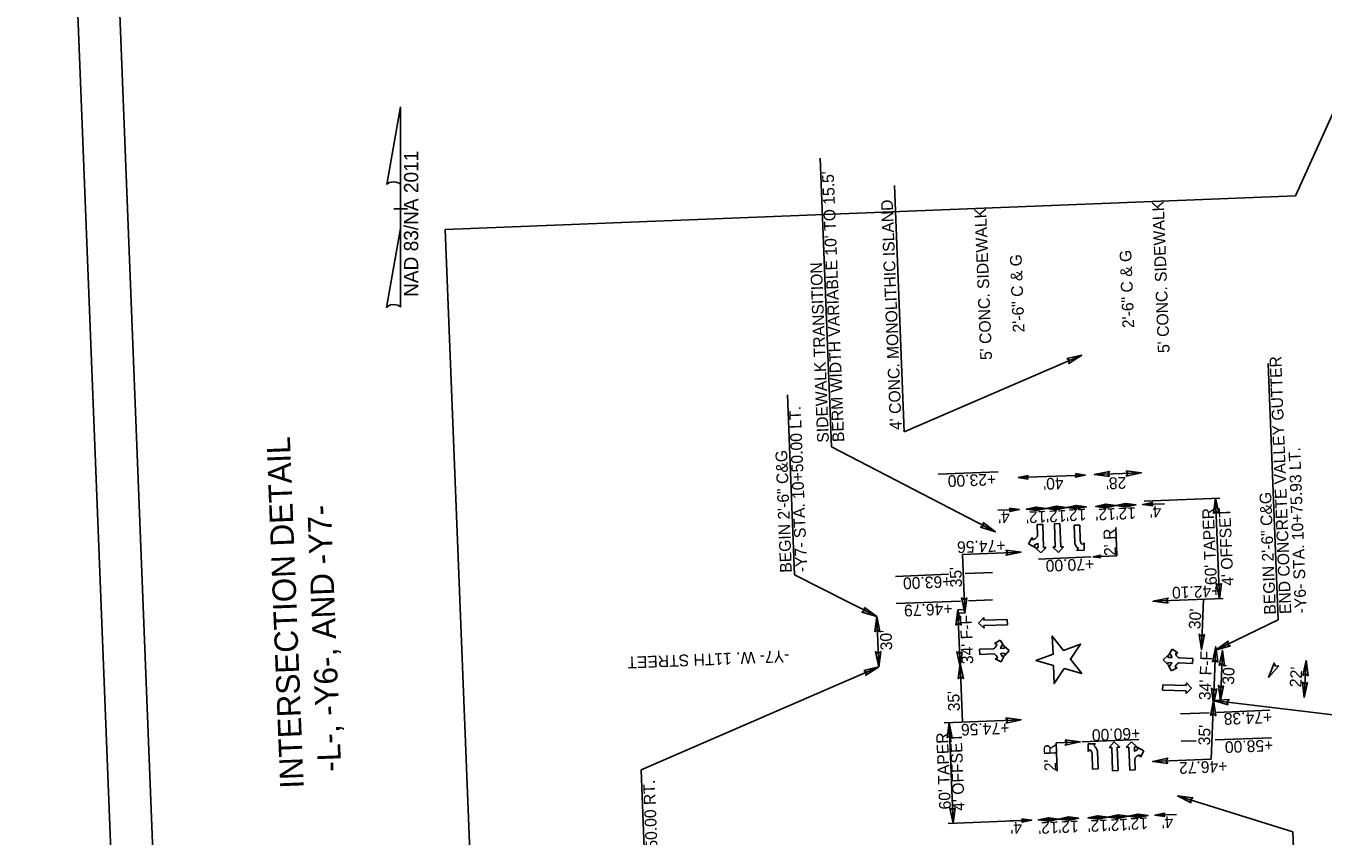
# Model space of a CAD drawing. Extents: x 1627811 to 1628977, y 762656 to 764629.
# Drawn here: x 1627811 to 1628584, y 763078 to 763561 of the extents above; entities that cross this region are included whole.
import ezdxf

# ---------------------------------------------------------------- set-up
doc = ezdxf.new("R2010")
doc.units = 0
for name, color, linetype in [('Prop Conc 2ft 6in Curb and Gutter', 7, 'Continuous'), ('Prop Dimension', 7, 'Continuous'), ('Prop Dimension Text', 7, 'Continuous'), ('Prop DSN Text', 7, 'Continuous'), ('Prop EOT', 7, 'Continuous'), ('Prop Lane Arrow CELL', 7, 'Continuous'), ('Prop North Arrow NAD83 for Plan Sheets CELL', 7, 'Continuous'), ('Prop RDY Traffic Signal CELL', 7, 'Continuous'), ('Prop Terminator CELL', 7, 'Continuous'), ('Sheet Clip Boundary CELL', 7, 'Continuous'), ('Sheet Plan And Profile CELL', 7, 'Continuous'), ('Sheet Plot Border Outside CELL', 7, 'Continuous')]:
    doc.layers.add(name, color=color, linetype=linetype)

msp = doc.modelspace()

# ---------------------------------------------------------------- linework, layer by layer
at = {"layer": 'Prop Conc 2ft 6in Curb and Gutter'}
for p, q in [((1628366.58, 763213.15), (1628370.61, 763213.31)), ((1628369.57, 763213.27), (1628369.61, 763213.27))]:
    msp.add_line(p, q, dxfattribs=at)
at = {"layer": 'Prop Dimension'}
for p, q in [((1628291.09, 763310.38), (1628284.3, 763482.61)), ((1628334.45, 763319.33), (1628328.65, 763466.35)), ((1628334.45, 763319.33), (1628440.42, 763365.19)), ((1628557.67, 763207.22), (1628551.64, 763360.16)), ((1628269.02, 763234.01), (1628264.79, 763341.42)), ((1628388.88, 763259.68), (1628291.09, 763310.38)), ((1628354.82, 763294.19), (1628390.49, 763295.6)), ((1628402.52, 763292.04), (1628442.49, 763293.62)), ((1628447.99, 763293.84), (1628475.96, 763294.94)), ((1628407.27, 763273.24), (1628419.26, 763273.71)), ((1628419.26, 763273.71), (1628431.25, 763274.19)), ((1628431.25, 763274.19), (1628443.24, 763274.66)), ((1628448.73, 763274.88), (1628460.72, 763275.35)), ((1628460.72, 763275.35), (1628472.72, 763275.82)), ((1628476.85, 763275.99), (1628489.72, 763276.49)), ((1628477.58, 763278.11), (1628522.84, 763279.9)), ((1628520.23, 763279.79), (1628522.6, 763219.84)), ((1628390.28, 763272.57), (1628403.27, 763273.08)), ((1628460.75, 763262.23), (1628461.41, 763245.35)), ((1628404.27, 763247.66), (1628369.3, 763246.28)), ((1628370.69, 763211.31), (1628369.3, 763246.28)), ((1628414.62, 763243.51), (1628445.78, 763244.74)), ((1628447.17, 763244.79), (1628461.41, 763245.35)), ((1628387.14, 763235.42), (1628370.91, 763234.78)), ((1628318.07, 763209.21), (1628269.02, 763234.01)), ((1628360.98, 763234.39), (1628329.24, 763233.14)), ((1628482.99, 763218.28), (1628524.77, 763219.93)), ((1628511.78, 763189.48), (1628512.97, 763219.46)), ((1628368.13, 763218.45), (1628329.63, 763216.93)), ((1628366.58, 763213.15), (1628367.93, 763179.17)), ((1628387.22, 763219.2), (1628372.94, 763218.64)), ((1628319.26, 763179.28), (1628318.07, 763209.18)), ((1628520.3, 763189.15), (1628557.67, 763207.22)), ((1628520.3, 763189.15), (1628519.03, 763157.17)), ((1628523.17, 763159.01), (1628524.36, 763188.98)), ((1628367.85, 763181.17), (1628369.24, 763146.2)), ((1628574.33, 763182.88), (1628573.11, 763160.91)), ((1628319.26, 763179.24), (1628177.51, 763117.78)), ((1628519.11, 763159.17), (1628517.72, 763124.2)), ((1628628.35, 763145.87), (1628519.11, 763159.17)), ((1628499.31, 763151.15), (1628516.34, 763151.82)), ((1628520.76, 763152), (1628552.65, 763153.26)), ((1628404.22, 763147.58), (1628358.25, 763145.77)), ((1628363.61, 763085.93), (1628361.25, 763145.88)), ((1628439.51, 763134.4), (1628425.09, 763133.84)), ((1628440.73, 763134.45), (1628474.48, 763135.78)), ((1628508.7, 763135.13), (1628499.76, 763134.78)), ((1628553.72, 763136.91), (1628520.1, 763135.58)), ((1628425.09, 763133.84), (1628425.75, 763116.96)), ((1628482.75, 763122.82), (1628517.72, 763124.2)), ((1628181.73, 763010.81), (1628177.51, 763117.78)), ((1628566.4, 763080.81), (1628497.61, 763102.15)), ((1628414.57, 763087.94), (1628426.56, 763088.41)), ((1628426.56, 763088.41), (1628438.55, 763088.89)), ((1628444.05, 763089.1), (1628456.04, 763089.58)), ((1628456.04, 763089.58), (1628468.03, 763090.05)), ((1628468.03, 763090.05), (1628480.02, 763090.52)), ((1628484.02, 763090.68), (1628496.89, 763091.19)), ((1628409.88, 763087.76), (1628360.62, 763085.81)), ((1628397.59, 763087.27), (1628410.58, 763087.78)), ((1628573.2, 762908.58), (1628566.4, 763080.81))]:
    msp.add_line(p, q, dxfattribs=at)
at = {"layer": 'Prop EOT'}
for p, q in [((1628366.66, 763211.15), (1628370.69, 763211.31)), ((1628369.65, 763211.27), (1628369.69, 763211.27))]:
    msp.add_line(p, q, dxfattribs=at)
at = {"layer": 'Prop Lane Arrow CELL'}
for p, q in [((1628413.83, 763264), (1628417.13, 763264.11)), ((1628414.06, 763257.55), (1628413.83, 763264)), ((1628417.13, 763264.11), (1628417.62, 763250.32)), ((1628424.13, 763264.57), (1628427.43, 763264.69)), ((1628424.63, 763250.58), (1628424.13, 763264.57)), ((1628427.43, 763264.69), (1628427.93, 763250.69)), ((1628439.21, 763263.77), (1628435.91, 763263.65)), ((1628435.91, 763263.65), (1628436.29, 763253.1)), ((1628439.54, 763254.62), (1628439.21, 763263.77)), ((1628408.69, 763252.5), (1628410.75, 763256.43)), ((1628412.62, 763250.44), (1628408.69, 763252.5)), ((1628410.75, 763256.43), (1628411.2, 763255.05)), ((1628412.16, 763251.88), (1628412.62, 763250.44)), ((1628414.32, 763250.2), (1628414.22, 763253.05)), ((1628423.14, 763250.52), (1628424.63, 763250.58)), ((1628426.45, 763247.49), (1628423.14, 763250.52)), ((1628429.43, 763250.75), (1628426.45, 763247.49)), ((1628427.93, 763250.69), (1628429.43, 763250.75)), ((1628441.79, 763253.25), (1628440.78, 763252.16)), ((1628441.9, 763248.75), (1628441.79, 763253.25)), ((1628412.83, 763250.15), (1628414.32, 763250.2)), ((1628416.09, 763247.17), (1628412.83, 763250.15)), ((1628419.12, 763250.38), (1628416.09, 763247.17)), ((1628417.62, 763250.32), (1628419.12, 763250.38)), ((1628438.51, 763249.73), (1628437.5, 763248.64)), ((1628437.5, 763248.64), (1628441.9, 763248.75)), ((1628378.88, 763205.25), (1628381.92, 763208.56)), ((1628382.13, 763202.26), (1628378.88, 763205.25)), ((1628381.92, 763208.56), (1628381.97, 763207.06)), ((1628381.97, 763207.06), (1628395.97, 763207.52)), ((1628396.08, 763204.23), (1628382.08, 763203.76)), ((1628395.97, 763207.52), (1628396.08, 763204.23)), ((1628382.08, 763203.76), (1628382.13, 763202.26)), ((1628379.5, 763189.64), (1628387.78, 763190)), ((1628379.63, 763186.62), (1628379.5, 763189.64)), ((1628388.43, 763193.05), (1628391.75, 763195.15)), ((1628389.71, 763192.72), (1628388.43, 763193.05)), ((1628391.75, 763195.15), (1628393.9, 763191.78)), ((1628391.77, 763190.17), (1628394.26, 763190.28)), ((1628393.9, 763191.78), (1628392.62, 763192.11)), ((1628394.26, 763190.28), (1628394.2, 763191.55)), ((1628394.2, 763191.55), (1628397.19, 763188.94)), ((1628397.19, 763188.94), (1628394.44, 763185.99)), ((1628492.28, 763186.3), (1628494.43, 763189.72)), ((1628494.43, 763189.72), (1628497.75, 763187.58)), ((1628387.86, 763186.98), (1628379.63, 763186.62)), ((1628388.82, 763183.99), (1628390.07, 763184.44)), ((1628392.32, 763182.14), (1628388.82, 763183.99)), ((1628394.39, 763187.26), (1628391.86, 763187.15)), ((1628394.16, 763185.74), (1628392.32, 763182.14)), ((1628392.91, 763185.29), (1628394.16, 763185.74)), ((1628394.44, 763185.99), (1628394.39, 763187.26)), ((1628488.99, 763183.36), (1628491.98, 763186.06)), ((1628491.75, 763180.51), (1628488.99, 763183.36)), ((1628491.8, 763181.78), (1628491.75, 763180.51)), ((1628494.28, 763181.67), (1628491.8, 763181.78)), ((1628491.98, 763186.06), (1628491.93, 763184.8)), ((1628491.93, 763184.8), (1628494.46, 763184.69)), ((1628493.57, 763186.63), (1628492.28, 763186.3)), ((1628497.75, 763187.58), (1628496.47, 763187.24)), ((1628506.56, 763181.15), (1628498.28, 763181.5)), ((1628498.45, 763184.52), (1628506.69, 763184.17)), ((1628506.69, 763184.17), (1628506.56, 763181.15)), ((1628493.88, 763176.71), (1628492.03, 763180.26)), ((1628492.03, 763180.26), (1628493.28, 763179.81)), ((1628497.37, 763178.52), (1628493.88, 763176.71)), ((1628496.12, 763178.96), (1628497.37, 763178.52)), ((1628488.69, 763165.25), (1628488.8, 763168.55)), ((1628488.8, 763168.55), (1628502.79, 763168.1)), ((1628505.88, 763166.4), (1628502.63, 763163.3)), ((1628502.79, 763168.1), (1628502.84, 763169.6)), ((1628502.84, 763169.6), (1628505.88, 763166.4)), ((1628502.68, 763164.8), (1628488.69, 763165.25)), ((1628502.63, 763163.3), (1628502.68, 763164.8)), ((1628456.77, 763131.12), (1628459.75, 763134.38)), ((1628459.75, 763134.38), (1628463.06, 763131.34)), ((1628467.01, 763131.3), (1628470.05, 763134.52)), ((1628470.05, 763134.52), (1628473.31, 763131.53)), ((1628448.57, 763133.31), (1628444.18, 763133.2)), ((1628444.18, 763133.2), (1628444.29, 763128.7)), ((1628444.29, 763128.7), (1628445.3, 763129.79)), ((1628446.54, 763127.33), (1628446.87, 763118.19)), ((1628447.56, 763132.22), (1628448.57, 763133.31)), ((1628450.16, 763118.3), (1628449.79, 763128.85)), ((1628458.27, 763131.17), (1628456.77, 763131.12)), ((1628458.77, 763117.18), (1628458.27, 763131.17)), ((1628463.06, 763131.34), (1628461.56, 763131.29)), ((1628461.56, 763131.29), (1628462.07, 763117.3)), ((1628468.51, 763131.36), (1628467.01, 763131.3)), ((1628469.01, 763117.57), (1628468.51, 763131.36)), ((1628473.31, 763131.53), (1628471.81, 763131.48)), ((1628471.81, 763131.48), (1628471.91, 763128.63)), ((1628473.97, 763129.8), (1628473.52, 763131.24)), ((1628473.52, 763131.24), (1628477.45, 763129.18)), ((1628475.38, 763125.25), (1628474.93, 763126.64)), ((1628477.45, 763129.18), (1628475.38, 763125.25)), ((1628472.07, 763124.13), (1628472.3, 763117.69)), ((1628446.87, 763118.19), (1628450.16, 763118.3)), ((1628462.07, 763117.3), (1628458.77, 763117.18)), ((1628472.3, 763117.69), (1628469.01, 763117.57))]:
    msp.add_line(p, q, dxfattribs=at)
for centre, radius, start, end in [((1628410.14, 763259.36), 4.43, 283.76826, 314.62182), ((1628411.11, 763256.2), 4.43, 283.64945, 314.52805), ((1628411.6, 763258.1), 2.52, 311.13173, 347.44373), ((1628441.43, 763254.08), 5.25, 190.73466, 236.04636), ((1628442.79, 763254.73), 3.28, 182.05859, 231.71676), ((1628386.99, 763192.13), 2.28, 290.42043, 323.41838), ((1628385.76, 763193.35), 4, 319.92829, 351.14097), ((1628388.67, 763192.7), 4, 320.73475, 351.51122), ((1628387.31, 763184.77), 2.28, 41.56467, 76.33069), ((1628386.19, 763183.45), 4, 14.12461, 45.05475), ((1628389.03, 763184.34), 4, 13.75542, 44.64511), ((1628497.16, 763178.89), 4, 135.81592, 166.59239), ((1628497.52, 763187.25), 4, 188.83659, 219.72628), ((1628500, 763177.99), 4, 135.00946, 166.22214), ((1628500.42, 763187.89), 4, 189.20578, 220.13593), ((1628498.88, 763179.31), 2.28, 105.50161, 138.49955), ((1628499.19, 763186.68), 2.28, 216.64584, 251.41186), ((1628443.28, 763127.22), 3.28, 2.05859, 51.71676), ((1628444.64, 763127.87), 5.25, 10.73466, 56.04636), ((1628475.02, 763125.48), 4.43, 103.64945, 134.52805), ((1628475.99, 763122.33), 4.43, 103.76826, 134.62182), ((1628474.54, 763123.58), 2.52, 131.13173, 167.44373)]:
    msp.add_arc(centre, radius, start, end, dxfattribs=at)
at = {"layer": 'Prop North Arrow NAD83 for Plan Sheets CELL'}
for p, q in [((1628025.77, 763466.96), (1628033.99, 763513.3)), ((1628034.04, 763513.3), (1628033.99, 763513.3)), ((1628034.04, 763513.3), (1628033.99, 763513.3)), ((1628034.04, 763513.3), (1628034.02, 763465.5)), ((1628034.01, 763440.7), (1628034.02, 763466.9)), ((1628034.02, 763465.5), (1628034.02, 763466.85)), ((1628030.02, 763452.3), (1628029.97, 763452.3)), ((1628033.57, 763452.3), (1628030.02, 763452.3)), ((1628030.07, 763452.3), (1628038.07, 763452.3)), ((1628034.01, 763440.7), (1628025.64, 763393.46)), ((1628034.04, 763393.65), (1628034.01, 763440.7))]:
    msp.add_line(p, q, dxfattribs=at)
for centre, start_param, end_param in [((1628029.91, 763466.46), 0.216388, 2.908219), ((1628029.88, 763393.29), 0.201328, 3.141593)]:
    msp.add_ellipse(centre, major_axis=(4.23, -0.03), ratio=0.461098, start_param=start_param, end_param=end_param, dxfattribs=at)
at = {"layer": 'Prop RDY Traffic Signal CELL'}
msp.add_lwpolyline([(1628423.53, 763179.98), (1628423.96, 763169.18), (1628429.96, 763178.17), (1628440.4, 763175.23), (1628433.68, 763183.74), (1628439.69, 763192.75), (1628429.54, 763189), (1628422.84, 763197.49), (1628423.27, 763186.68), (1628413.1, 763182.92), (1628423.53, 763179.98)], dxfattribs=at)
at = {"layer": 'Prop Terminator CELL'}
for points in [[(1628431.54, 763363.04), (1628440.42, 763365.19), (1628432.75, 763360.12), (1628433.17, 763362.05)], [(1628408.4, 763291.21), (1628402.52, 763292.04), (1628408.37, 763293.26), (1628407.65, 763292.2)], [(1628436.61, 763294.45), (1628442.49, 763293.62), (1628436.64, 763292.4), (1628437.36, 763293.47)], [(1628457.04, 763292.64), (1628447.99, 763293.84), (1628456.97, 763295.79), (1628455.88, 763294.15)], [(1628466.91, 763296.14), (1628475.96, 763294.94), (1628466.98, 763292.99), (1628468.07, 763294.63)], [(1628397.38, 763273.86), (1628403.27, 763273.08), (1628397.43, 763271.81), (1628398.14, 763272.88)], [(1628413.15, 763272.47), (1628407.27, 763273.24), (1628413.1, 763274.51), (1628412.4, 763273.44)], [(1628413.37, 763274.49), (1628419.26, 763273.71), (1628413.42, 763272.44), (1628414.13, 763273.51)], [(1628425.14, 763272.94), (1628419.26, 763273.71), (1628425.09, 763274.99), (1628424.39, 763273.92)], [(1628425.36, 763274.96), (1628431.25, 763274.19), (1628425.41, 763272.92), (1628426.12, 763273.98)], [(1628437.13, 763273.41), (1628431.25, 763274.19), (1628437.08, 763275.46), (1628436.38, 763274.39)], [(1628437.35, 763275.44), (1628443.24, 763274.66), (1628437.4, 763273.39), (1628438.11, 763274.46)], [(1628454.62, 763274.1), (1628448.73, 763274.88), (1628454.57, 763276.15), (1628453.87, 763275.08)], [(1628454.84, 763276.13), (1628460.72, 763275.35), (1628454.89, 763274.08), (1628455.59, 763275.15)], [(1628466.61, 763274.57), (1628460.72, 763275.35), (1628466.56, 763276.62), (1628465.86, 763275.55)], [(1628466.83, 763276.6), (1628472.72, 763275.82), (1628466.88, 763274.55), (1628467.58, 763275.62)], [(1628482.74, 763275.21), (1628476.85, 763275.99), (1628482.69, 763277.26), (1628481.98, 763276.19)], [(1628519.04, 763270.74), (1628520.23, 763279.79), (1628522.19, 763270.81), (1628520.54, 763271.9)], [(1628381.6, 763265.2), (1628388.88, 763259.68), (1628380.1, 763262.42), (1628381.86, 763263.31)], [(1628395.22, 763248.85), (1628404.27, 763247.66), (1628395.29, 763245.71), (1628396.38, 763247.35)], [(1628451.7, 763244.19), (1628447.17, 763244.79), (1628451.66, 763245.77), (1628451.12, 763244.95)], [(1628523.79, 763228.89), (1628522.6, 763219.84), (1628520.64, 763228.82), (1628522.29, 763227.73)], [(1628371.88, 763220.36), (1628370.69, 763211.31), (1628368.73, 763220.29), (1628370.38, 763219.2)], [(1628492.04, 763217.08), (1628482.99, 763218.28), (1628491.97, 763220.23), (1628490.88, 763218.59)], [(1628310.73, 763214.66), (1628318.07, 763209.21), (1628309.27, 763211.87), (1628311.02, 763212.78)], [(1628365.39, 763204.09), (1628366.58, 763213.15), (1628368.54, 763204.17), (1628366.89, 763205.25)], [(1628316.88, 763200.16), (1628318.07, 763209.21), (1628320.03, 763200.23), (1628318.38, 763201.32)], [(1628513.68, 763198.41), (1628511.78, 763189.48), (1628510.54, 763198.59), (1628512.09, 763197.38)], [(1628518.47, 763182.21), (1628520.38, 763191.14), (1628521.62, 763182.04), (1628520.06, 763183.25)], [(1628529.08, 763191.67), (1628520.3, 763189.15), (1628527.75, 763194.53), (1628527.41, 763192.59)], [(1628522.46, 763180.05), (1628524.36, 763188.98), (1628525.6, 763179.88), (1628524.05, 763181.09)], [(1628320.45, 763188.29), (1628319.26, 763179.24), (1628317.3, 763188.22), (1628318.95, 763187.13)], [(1628369.12, 763188.23), (1628367.93, 763179.17), (1628365.97, 763188.15), (1628367.62, 763187.07)], [(1628366.66, 763172.12), (1628367.85, 763181.17), (1628369.81, 763172.19), (1628368.16, 763173.28)], [(1628557.91, 763179.71), (1628551.84, 763172.88), (1628555.26, 763181.41), (1628556.02, 763179.59)], [(1628572.29, 763173.98), (1628574.33, 763182.88), (1628575.43, 763173.75), (1628573.89, 763174.99)], [(1628310.39, 763177.08), (1628319.26, 763179.24), (1628311.59, 763174.17), (1628312.01, 763176.09)], [(1628520.94, 763166.1), (1628519.03, 763157.17), (1628517.79, 763166.28), (1628519.34, 763165.06)], [(1628525.08, 763167.94), (1628523.17, 763159.01), (1628521.93, 763168.11), (1628523.49, 763166.9)], [(1628575.16, 763169.81), (1628573.11, 763160.91), (1628572.02, 763170.03), (1628573.55, 763168.8)], [(1628517.21, 763150.24), (1628519.11, 763159.17), (1628520.35, 763150.06), (1628518.8, 763151.28)], [(1628527.86, 763156.54), (1628519.11, 763159.17), (1628528.29, 763159.66), (1628526.95, 763158.21)], [(1628360.05, 763136.83), (1628361.25, 763145.88), (1628363.2, 763136.9), (1628361.56, 763137.99)], [(1628395.16, 763148.77), (1628404.22, 763147.58), (1628395.24, 763145.62), (1628396.32, 763147.27)], [(1628430.46, 763135.6), (1628439.51, 763134.4), (1628430.53, 763132.45), (1628431.62, 763134.09)], [(1628491.81, 763121.62), (1628482.75, 763122.82), (1628491.73, 763124.77), (1628490.65, 763123.13)], [(1628505.75, 763098.01), (1628497.61, 763102.15), (1628506.73, 763101), (1628505.16, 763099.81)], [(1628364.81, 763094.99), (1628363.61, 763085.93), (1628361.66, 763094.91), (1628363.3, 763093.83)], [(1628404.69, 763088.56), (1628410.58, 763087.78), (1628404.74, 763086.51), (1628405.45, 763087.58)], [(1628420.46, 763087.16), (1628414.57, 763087.94), (1628420.41, 763089.21), (1628419.7, 763088.14)], [(1628420.68, 763089.19), (1628426.56, 763088.41), (1628420.73, 763087.14), (1628421.43, 763088.21)], [(1628432.45, 763087.64), (1628426.56, 763088.41), (1628432.4, 763089.68), (1628431.69, 763088.62)], [(1628432.67, 763089.66), (1628438.55, 763088.89), (1628432.72, 763087.62), (1628433.42, 763088.68)], [(1628449.94, 763088.33), (1628444.05, 763089.1), (1628449.89, 763090.37), (1628449.18, 763089.31)], [(1628450.16, 763090.35), (1628456.04, 763089.58), (1628450.2, 763088.3), (1628450.91, 763089.37)], [(1628461.93, 763088.8), (1628456.04, 763089.58), (1628461.88, 763090.85), (1628461.17, 763089.78)], [(1628462.15, 763090.82), (1628468.03, 763090.05), (1628462.19, 763088.78), (1628462.9, 763089.85)], [(1628473.92, 763089.27), (1628468.03, 763090.05), (1628473.87, 763091.32), (1628473.16, 763090.25)], [(1628474.14, 763091.3), (1628480.02, 763090.52), (1628474.19, 763089.25), (1628474.89, 763090.32)], [(1628489.9, 763089.9), (1628484.02, 763090.68), (1628489.86, 763091.95), (1628489.15, 763090.88)]]:
    msp.add_lwpolyline(points, close=True, dxfattribs=at)
at = {"layer": 'Sheet Clip Boundary CELL'}
msp.add_lwpolyline([(1628080.25, 762943.5), (1628060.66, 763440.11), (1628567.89, 763460.11), (1628623.39, 763582.83), (1628623.86, 763610.17), (1628631.44, 763609.98), (1628639.19, 763612.32), (1628786.08, 763468.72), (1628805.66, 762972.11)], close=True, dxfattribs=at)
at = {"layer": 'Sheet Plan And Profile CELL'}
msp.add_lwpolyline([(1627836.47, 764330.65), (1627895.58, 762831.81), (1628944.76, 762873.18), (1628885.66, 764372.02)], close=True, dxfattribs=at)
at = {"layer": 'Sheet Plot Border Outside CELL'}
msp.add_lwpolyline([(1628976.64, 762699.3), (1628909.65, 764397.98), (1627810.51, 764354.64), (1627877.49, 762655.96)], close=True, dxfattribs=at)

# ---------------------------------------------------------------- texts
at = {"layer": 'Prop Dimension'}
for s, height, rotation, p in [('INTERSECTION DETAIL', 14, 92.25819, (1627976.26, 763106.8)), ('-L-, -Y6-, AND -Y7-', 14, 92.25819, (1627998.63, 763116.91)), ("60' TAPER", 7, 92.42255, (1628521.12, 763228.11)), ("4' OFFSET", 7, 92.42255, (1628531.01, 763227.71)), ('+70.00', 7, 182.25819, (1628447.64, 763244)), ('+60.00', 7, 182.25819, (1628475.18, 763142.98))]:
    msp.add_text(s, height=height, rotation=rotation, dxfattribs=at).set_placement(p)
at = {"layer": 'Prop Dimension Text'}
for s, rotation, p in [("BERM WIDTH VARIABLE 10' TO 15.5'", 92.25819, (1628298.76, 763313.41)), ('SIDEWALK TRANSITION', 92.25819, (1628289.59, 763313.05)), ('END CONCRETE VALLEY GUTTER', 92.25819, (1628565.46, 763210.82)), ('-Y7- STA. 10+50.00 LT.', 92.25819, (1628276.66, 763235.83)), ('BEGIN 2\'-6" C&G', 92.25819, (1628267.49, 763235.46)), ('-Y6- STA. 10+75.93 LT.', 92.25819, (1628574.62, 763211.19)), ('+23.00', 182.25819, (1628389.21, 763294.53)), ("40'", 182.25819, (1628429.45, 763292.24)), ("28'", 182.25819, (1628466.84, 763292.5)), ('BEGIN 2\'-6" C&G', 92.25819, (1628556.29, 763210.46)), ("12'", 182.25819, (1628460.63, 763273.93)), ("12'", 182.25819, (1628472.62, 763274.4)), ("4'", 182.25819, (1628487.72, 763275.45)), ("4'", 182.25819, (1628397.38, 763272.13)), ("12'", 182.25819, (1628419.16, 763272.29)), ("12'", 182.25819, (1628431.15, 763272.77)), ("12'", 182.25819, (1628443.01, 763273.52)), ("2' R", 92.05859, (1628460.86, 763245.48)), ('+74.56', 182.25819, (1628394.76, 763255.1)), ("35'", 92.05859, (1628369.02, 763226.7)), ('+63.00', 182.25819, (1628362.5, 763233.57)), ('+42.10', 182.25819, (1628523.01, 763227.97)), ('+46.79', 182.25819, (1628363.14, 763217.34)), ("30'", 86.56048, (1628511.14, 763201.46)), ("34' F-F", 92.05859, (1628375.73, 763180.91)), ("30' ", 92.05859, (1628327.38, 763189.17)), ("34' F-F", 88.02648, (1628517.27, 763159.19)), ("30'", 88.02648, (1628531.29, 763168.44)), ("22'", 86.82578, (1628571.38, 763166.79)), ("35'", 92.05859, (1628367.77, 763152.81)), ('+74.38', 182.25819, (1628553.88, 763152.66)), ('+74.56', 182.25819, (1628397.11, 763146.2)), ("35'", 88.02648, (1628516.91, 763132.25)), ("60' TAPER", 92.25819, (1628362.36, 763094.24)), ("4' OFFSET", 92.25819, (1628370.6, 763093.44)), ('+58.00', 182.25819, (1628554.54, 763135.86)), ("2' R", 92.05859, (1628425.2, 763117.08)), ('+46.72', 182.25819, (1628527.18, 763123.42)), ('-Y7- STA. 10+50.00 RT.', 92.25819, (1628189.65, 763011.35)), ("12'", 182.25819, (1628455.95, 763088.16)), ("12'", 182.25819, (1628467.94, 763088.63)), ("12'", 182.25819, (1628479.8, 763089.38)), ("4'", 182.25819, (1628494.89, 763090.15)), ("4'", 182.25819, (1628404.69, 763086.83)), ("12'", 182.25819, (1628426.47, 763086.99)), ("12'", 182.25819, (1628438.46, 763087.47))]:
    msp.add_text(s, height=7, rotation=rotation, dxfattribs=at).set_placement(p)
at = {"layer": 'Prop DSN Text'}
for s, rotation, p in [("4' CONC. MONOLITHIC ISLAND", 92.25819, (1628333.04, 763320.63)), ("5' CONC. SIDEWALK", 92.25819, (1628386.92, 763362.39)), ("5' CONC. SIDEWALK", 92.25819, (1628492.89, 763366.57)), ('2\'-6" C & G', 92.25819, (1628406.31, 763378.81)), ('2\'-6" C & G', 92.25819, (1628471.75, 763381.39)), ('-Y7- W. 11TH STREET', 182.28019, (1628265.8, 763189.02))]:
    msp.add_text(s, height=7, rotation=rotation, dxfattribs=at).set_placement(p)
at = {"layer": 'Prop North Arrow NAD83 for Plan Sheets CELL'}
msp.add_text('NAD 83/NA 2011', height=8.5, rotation=89.97566, dxfattribs=at).set_placement((1628044.52, 763399.87))

doc.saveas('drawing.dxf')
